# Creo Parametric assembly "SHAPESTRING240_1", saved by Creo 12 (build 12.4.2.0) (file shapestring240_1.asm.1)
Units: Custom; MM, KILOGRAM, SECS

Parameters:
  PTC_WM_ITERATION = "0"
  PTC_WM_VERSION = "-.0"
  PTC_WM_LIFECYCLE_STATE = "In Work"
  PTC_WM_LIFECYCLE = "MO_CADDocument"
  PTC_WM_CREATED_BY = "Maximilian Roepper (Z0017RMS: MO)"
  PTC_WM_CREATED_ON = "18-Sep-26 11:36:42 AM"
  PTC_WM_MODIFIED_BY = "Maximilian Roepper (Z0017RMS: MO)"
  PTC_WM_MODIFIED_ON = "18-Sep-26 11:36:46 AM"
  PDMLINKNUMBER = "PDM000071454771"
  PTC_WM_NAME = "shapestring240_1.asm"
  PTC_WM_NUMBER = "PDM000071454771"

Other parameters: WEIGHT, WEIGHT_FACTOR, WEIGHT_ADD, MC_ERRORS, SUPPLIER, ISPOSITIONINGASSEMBLY

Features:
  1. coordinate system
  2. imported feature
  3. component "SHAPESTRING095_1"
  4. component "SHAPESTRING239_1"

Other named items: DRW_VIEW_ORG, ROUGH-GROB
